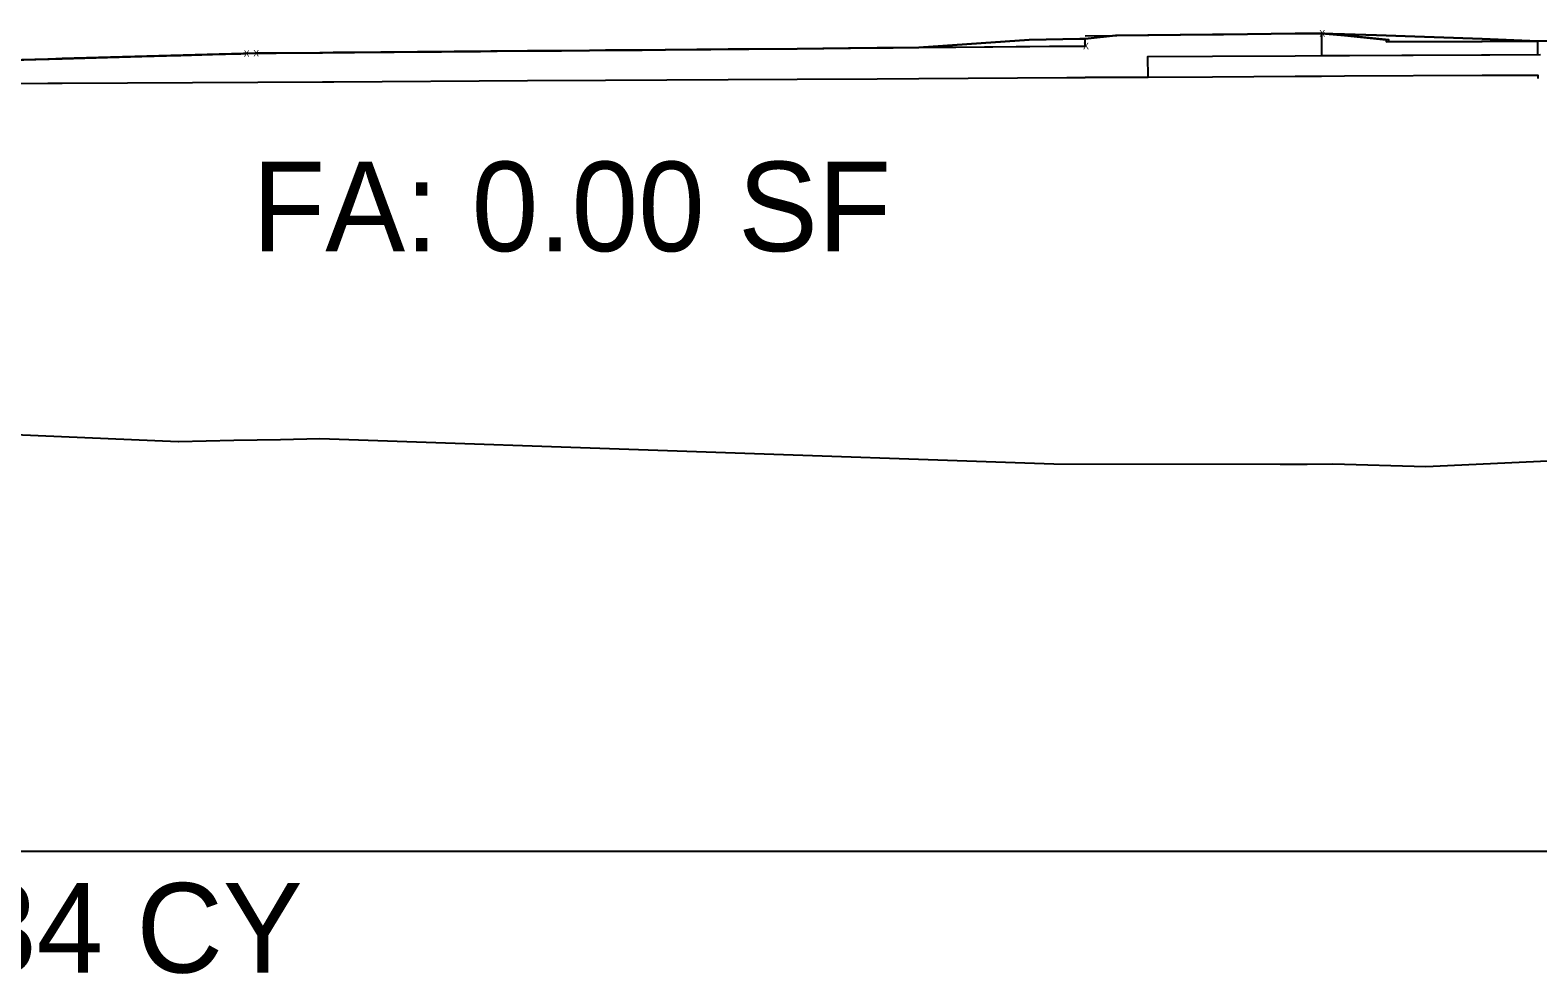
# Model space of a CAD drawing. Extents: x -26 to 303, y -16 to 6048.
# Drawn here: x 30.9 to 87.4, y 5995.4 to 6030.8 of the extents above; entities that cross this region are included whole.
import ezdxf

# ---------------------------------------------------------------- set-up
doc = ezdxf.new("R2010")
doc.units = 0
for name, color, linetype in [('CONST_LV3', 7, 'Continuous'), ('DTM_P_FINISHED_GRADE', 7, 'Continuous'), ('DTM_P_FINISHED_GRADE2', 7, 'Continuous'), ('DTM_X_GROUND', 7, 'Continuous'), ('TRANS_EOP_PAVED', 7, 'Continuous'), ('XS_CELL', 7, 'Continuous'), ('XS_M_SHAPES_EARTHWORK', 7, 'Continuous'), ('XS_P_CONCRETE', 7, 'Continuous'), ('XS_P_GROUND', 7, 'Continuous'), ('XS_P_SHOULDER', 7, 'Continuous'), ('XS_P_SUBGRADE_GRANULAR', 7, 'Continuous'), ('XS_P_SUBGRADE_GRANULAR_B', 7, 'Continuous'), ('XS_SHEET_EW_TX_AREA', 7, 'Continuous'), ('XS_SHEET_EW_TX_VOLUME', 7, 'Continuous')]:
    doc.layers.add(name, color=color, linetype=linetype)

msp = doc.modelspace()

# ---------------------------------------------------------------- linework, layer by layer
at = {"layer": 'CONST_LV3'}
for points in [[(70.459, 6030.583), (75.235, 6030.63), (75.24, 6030.63), (75.297, 6030.63), (75.331, 6030.63), (75.462, 6030.632), (78.284, 6030.666), (78.332, 6030.666), (79.325, 6030.675)], [(70.459, 6030.583), (71.595, 6030.594), (75.235, 6030.63), (75.236, 6030.63), (75.24, 6030.63), (75.248, 6030.63), (75.297, 6030.63), (75.302, 6030.63), (75.331, 6030.63), (75.35, 6030.631), (75.462, 6030.632), (75.812, 6030.636), (78.284, 6030.666), (78.286, 6030.666), (78.332, 6030.666), (78.398, 6030.667), (79.325, 6030.675)], [(70.459, 6030.583), (71.6, 6030.594), (75.24, 6030.629), (75.642, 6030.634), (78.332, 6030.662), (78.398, 6030.662), (79.325, 6030.673)], [(79.325, 6030.675), (79.325, 6029.842), (80.178, 6029.844), (80.182, 6029.844), (80.278, 6029.844), (80.372, 6029.845), (82.333, 6029.854), (85.328, 6029.87), (85.346, 6029.871), (85.497, 6029.87), (85.645, 6029.871), (87.542, 6029.879)], [(87.542, 6030.379), (85.645, 6030.371), (85.497, 6030.37), (85.346, 6030.371), (85.328, 6030.37), (82.333, 6030.354), (81.861, 6030.351), (81.856, 6030.435), (80.372, 6030.58), (80.278, 6030.588), (80.182, 6030.598), (80.178, 6030.598), (79.325, 6030.675)], [(38.968, 6029.915), (41.244, 6029.936), (41.325, 6029.936), (42.744, 6029.949), (43.043, 6029.952), (46.026, 6029.98), (46.31, 6029.982), (47.769, 6029.996), (48.395, 6030.001), (50.808, 6030.022), (51.34, 6030.027), (52.794, 6030.039), (52.864, 6030.04), (53.026, 6030.041), (53.841, 6030.048), (55.59, 6030.063), (56.412, 6030.07), (57.818, 6030.082), (58.882, 6030.091), (60.371, 6030.104), (61.526, 6030.114), (62.843, 6030.126), (64.03, 6030.137), (65.152, 6030.151), (66.678, 6030.164), (67.866, 6030.176), (69.12, 6030.187), (69.932, 6030.194), (70.459, 6030.199)], [(72.815, 6029.032), (72.81, 6029.803), (75.24, 6029.817), (78.332, 6029.834), (79.325, 6029.839)]]:
    msp.add_lwpolyline(points, dxfattribs=at)
at = {"layer": 'DTM_P_FINISHED_GRADE'}
msp.add_lwpolyline([(87.441, 6030.379), (90.504, 6030.396)], dxfattribs=at)
at = {"layer": 'DTM_P_FINISHED_GRADE2'}
msp.add_lwpolyline([(39.326, 6029.925), (39.403, 6029.926), (39.413, 6029.926), (39.416, 6029.926), (41.841, 6029.946), (42.247, 6029.949), (42.267, 6029.95), (42.66, 6029.953), (49.534, 6030.011), (51.864, 6030.031), (52.459, 6030.036), (53.519, 6030.045), (57.062, 6030.075), (57.841, 6030.082), (59.655, 6030.098), (61.572, 6030.115), (62.654, 6030.124), (63.259, 6030.13), (64.213, 6030.138), (68.357, 6030.433), (70.258, 6030.467), (70.412, 6030.47), (70.459, 6030.471), (71.6, 6030.594), (75.24, 6030.629), (75.642, 6030.634), (78.332, 6030.662), (78.398, 6030.662), (79.325, 6030.673), (80.183, 6030.597), (81.753, 6030.435), (81.755, 6030.409), (81.758, 6030.352), (83.67, 6030.361), (85.346, 6030.37), (87.441, 6030.379), (90.504, 6030.396)], dxfattribs=at)
at = {"layer": 'DTM_X_GROUND'}
for points in [[(29.568, 6029.654), (31.534, 6029.708), (31.588, 6029.71), (32.079, 6029.724), (32.736, 6029.742), (39.326, 6029.925), (39.403, 6029.926), (39.413, 6029.926), (41.745, 6029.945), (41.841, 6029.946), (42.247, 6029.949), (42.267, 6029.95), (42.66, 6029.953), (49.534, 6030.011), (51.864, 6030.031), (52.459, 6030.036), (53.519, 6030.045), (57.062, 6030.075), (57.841, 6030.082), (59.655, 6030.098), (61.572, 6030.115), (62.654, 6030.124), (63.259, 6030.13), (64.213, 6030.138), (68.357, 6030.433), (70.258, 6030.467), (70.412, 6030.47), (70.459, 6030.471), (71.6, 6030.594), (75.24, 6030.629), (75.642, 6030.634), (78.332, 6030.662), (78.398, 6030.662), (79.325, 6030.673), (80.183, 6030.648), (81.385, 6030.606), (85.346, 6030.469), (87.441, 6030.379), (90.504, 6030.396)], [(0, 6016.56), (1.34, 6016.547), (4.962, 6016.503), (11.333, 6016.44), (36.428, 6015.365), (36.445, 6015.366), (38.521, 6015.406), (40.261, 6015.44), (41.739, 6015.469), (69.286, 6014.527), (77.777, 6014.513), (78.789, 6014.517), (79.749, 6014.521), (83.233, 6014.422), (116.875, 6015.983)]]:
    msp.add_lwpolyline(points, dxfattribs=at)
at = {"layer": 'XS_CELL'}
msp.add_line((0, 6000), (150, 6000), dxfattribs=at)
at = {"layer": 'XS_M_SHAPES_EARTHWORK'}
for points in [[(89.151, 6030.389), (87.441, 6030.379), (85.346, 6030.469), (81.385, 6030.606), (80.183, 6030.648), (79.325, 6030.673), (78.398, 6030.662), (78.332, 6030.662), (75.642, 6030.634), (75.24, 6030.629), (71.6, 6030.594), (70.459, 6030.471), (70.412, 6030.47), (70.258, 6030.467), (68.357, 6030.433), (64.213, 6030.138), (63.259, 6030.13), (62.654, 6030.124), (61.572, 6030.115), (59.655, 6030.098), (57.841, 6030.082), (57.062, 6030.075), (53.519, 6030.045), (52.459, 6030.036), (51.864, 6030.031), (49.534, 6030.011), (42.66, 6029.953), (42.267, 6029.95), (42.247, 6029.949), (41.841, 6029.946), (41.745, 6029.945), (39.413, 6029.926), (39.403, 6029.926), (39.326, 6029.925), (32.736, 6029.742), (32.079, 6029.724), (31.588, 6029.71), (31.534, 6029.708), (29.568, 6029.654)], [(29.292, 6028.792), (31.534, 6028.803), (32.079, 6028.806), (39.413, 6028.844), (41.841, 6028.857), (42.267, 6028.859), (49.534, 6028.899), (52.459, 6028.915), (57.062, 6028.939), (59.655, 6028.954), (62.654, 6028.972), (64.213, 6028.98), (69.775, 6029.013), (70.298, 6029.017), (70.459, 6029.018), (72.815, 6029.032), (75.24, 6029.046), (78.332, 6029.063), (79.325, 6029.068), (80.183, 6029.073), (85.346, 6029.099), (87.441, 6029.109), (87.441, 6028.984)]]:
    msp.add_lwpolyline(points, dxfattribs=at)
for points in [[(69.775, 6030.188), (70.298, 6030.193), (70.459, 6030.194), (70.459, 6030.471), (70.412, 6030.47), (70.258, 6030.467), (68.357, 6030.433), (64.213, 6030.138)], [(32.079, 6029.724), (32.736, 6029.742), (39.326, 6029.925)]]:
    msp.add_lwpolyline(points, close=True, dxfattribs=at)
at = {"layer": 'XS_P_CONCRETE'}
msp.add_lwpolyline([(79.325, 6030.673), (79.325, 6029.839), (80.183, 6029.844), (85.346, 6029.87), (87.441, 6029.879), (87.441, 6030.379), (85.346, 6030.37), (81.758, 6030.352), (81.753, 6030.435), (80.183, 6030.597), (79.325, 6030.673)], dxfattribs=at)
at = {"layer": 'XS_P_GROUND'}
for points in [[(0, 6028.851), (1.531, 6028.892), (6.026, 6029.012), (9.05, 6029.094), (11.71, 6029.166), (19.171, 6029.368), (19.391, 6029.374), (20.106, 6029.394), (21.893, 6029.443), (24.214, 6029.507), (25.995, 6029.555), (26.456, 6029.568), (29.292, 6029.646), (31.534, 6029.708), (32.079, 6029.723), (39.326, 6029.925)], [(28.474, 6029.622), (31.68, 6029.711), (31.82, 6029.715), (32.693, 6029.739), (33.163, 6029.753), (36.462, 6029.845), (36.526, 6029.847), (37.719, 6029.88), (38.685, 6029.907), (38.778, 6029.91), (38.968, 6029.915)]]:
    msp.add_lwpolyline(points, dxfattribs=at)
at = {"layer": 'XS_P_SHOULDER'}
for points in [[(70.459, 6030.583), (75.24, 6030.629), (78.332, 6030.662), (79.325, 6030.673)], [(39.326, 6029.925), (39.413, 6029.926), (41.841, 6029.946), (42.267, 6029.95), (49.534, 6030.011), (52.459, 6030.036), (57.062, 6030.075), (59.655, 6030.098), (62.654, 6030.124), (64.213, 6030.138), (69.775, 6030.188), (70.298, 6030.193), (70.459, 6030.194)]]:
    msp.add_lwpolyline(points, dxfattribs=at)
at = {"layer": 'XS_P_SUBGRADE_GRANULAR'}
for points in [[(29.292, 6028.792), (31.534, 6028.803), (32.079, 6028.806), (39.413, 6028.844), (41.841, 6028.857), (42.267, 6028.859), (49.534, 6028.899), (52.459, 6028.915), (57.062, 6028.939), (59.655, 6028.954), (62.654, 6028.972), (64.213, 6028.98), (69.775, 6029.013), (70.298, 6029.017), (70.459, 6029.018)], [(72.815, 6029.032), (75.24, 6029.046), (78.332, 6029.063), (79.325, 6029.068)], [(79.325, 6029.068), (80.183, 6029.073), (85.346, 6029.099), (87.441, 6029.109)]]:
    msp.add_lwpolyline(points, dxfattribs=at)
at = {"layer": 'XS_P_SUBGRADE_GRANULAR_B'}
msp.add_lwpolyline([(72.815, 6029.032), (70.459, 6029.018)], dxfattribs=at)

# ---------------------------------------------------------------- texts
at = {"layer": 'TRANS_EOP_PAVED'}
for p in [(38.889, 6029.795), (70.38, 6030.079), (70.38, 6030.079)]:
    msp.add_text('X', height=0.24, dxfattribs=at).set_placement(p)
at = {"layer": 'XS_P_GROUND'}
for p in [(79.246, 6030.553), (39.248, 6029.805)]:
    msp.add_text('X', height=0.24, dxfattribs=at).set_placement(p)
at = {"layer": 'XS_SHEET_EW_TX_AREA'}
msp.add_text('FA: 0.00 SF', height=3.36, dxfattribs=at).set_placement((39.202, 6022.5))
at = {"layer": 'XS_SHEET_EW_TX_VOLUME'}
msp.add_text('FV: 47.34 CY', height=3.36, dxfattribs=at).set_placement((14.13, 5995.44))

doc.saveas('drawing.dxf')
